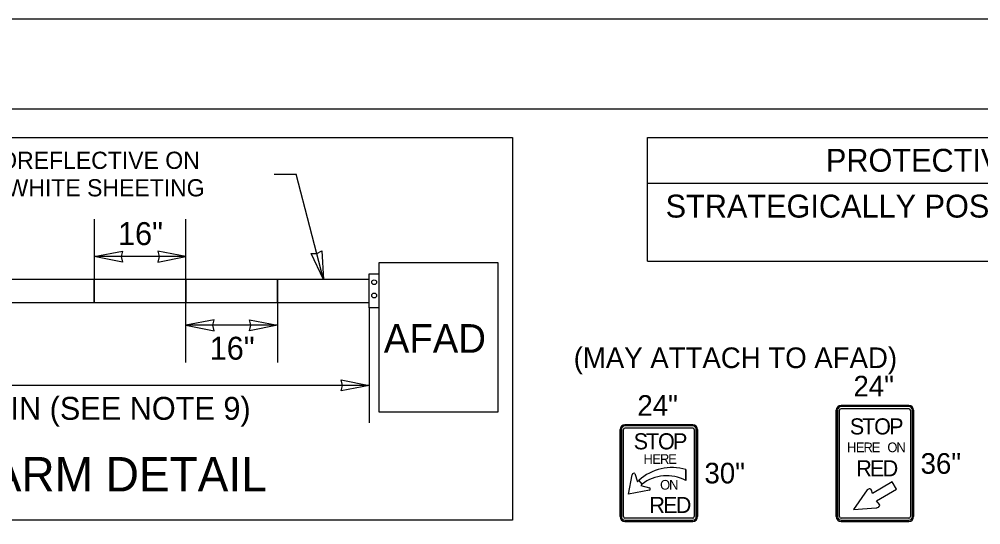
# Model space of a CAD drawing. Extents: x 99999.1 to 100095.7, y 99995 to 100010.7.
# Drawn here: x 100009.243 to 100012.598, y 100008.923 to 100010.687 of the extents above; entities that cross this region are included whole.
import ezdxf

# ---------------------------------------------------------------- set-up
doc = ezdxf.new("R2010")
doc.units = 0
for name, color, linetype in [('SH_GI_PlotLimits', 7, 'Continuous'), ('SH_GI_SheetBorder', 7, 'Continuous'), ('SH_TI_Tables', 7, 'Continuous'), ('TR_SN_ConstructionSigns', 7, 'Continuous'), ('TR_WZ_WorkZoneDetails', 7, 'Continuous')]:
    doc.layers.add(name, color=color, linetype=linetype)

msp = doc.modelspace()

# ---------------------------------------------------------------- linework, layer by layer
at = {"layer": 'SH_GI_PlotLimits'}
msp.add_lwpolyline([(99999.0625, 99999.6875), (100016.0625, 99999.6875), (100016.0625, 100010.6875), (99999.0625, 100010.6875)], close=True, dxfattribs=at)
at = {"layer": 'SH_GI_SheetBorder'}
msp.add_line((100000, 100010.375), (100015.75, 100010.375), dxfattribs=at)
at = {"layer": 'SH_TI_Tables'}
for p, q in [((100011.4347, 100009.843), (100011.4347, 100010.275)), ((100011.4347, 100010.275), (100015.65, 100010.275)), ((100011.4347, 100010.115), (100015.65, 100010.115)), ((100011.4347, 100009.843), (100015.65, 100009.843))]:
    msp.add_line(p, q, dxfattribs=at)
at = {"layer": 'TR_SN_ConstructionSigns'}
for p, q in [((100012.0939, 100009.3222), (100012.0939, 100008.951)), ((100012.0939, 100008.951), (100012.0939, 100009.3222)), ((100012.0939, 100009.3222), (100012.0939, 100008.951)), ((100012.0981, 100009.3222), (100012.0981, 100008.951)), ((100012.1052, 100008.951), (100012.1052, 100009.3222)), ((100012.347, 100009.3391), (100012.1108, 100009.3391)), ((100012.1108, 100009.3391), (100012.347, 100009.3391)), ((100012.347, 100009.3391), (100012.1108, 100009.3391)), ((100012.347, 100009.3349), (100012.1108, 100009.3349)), ((100012.1108, 100009.3279), (100012.347, 100009.3279)), ((100012.3527, 100009.3222), (100012.3527, 100008.951)), ((100012.3597, 100008.951), (100012.3597, 100009.3222)), ((100012.3639, 100008.951), (100012.3639, 100009.3222)), ((100012.3639, 100009.3222), (100012.3639, 100008.951)), ((100012.3639, 100008.951), (100012.3639, 100009.3222)), ((100011.3397, 100009.2547), (100011.3397, 100008.951)), ((100011.3397, 100008.951), (100011.3397, 100009.2547)), ((100011.3397, 100009.2547), (100011.3397, 100008.951)), ((100011.3397, 100008.951), (100011.3397, 100009.2547)), ((100011.3439, 100009.2547), (100011.3439, 100008.951)), ((100011.351, 100008.951), (100011.351, 100009.2547)), ((100011.5928, 100009.2716), (100011.3566, 100009.2716)), ((100011.3566, 100009.2716), (100011.5928, 100009.2716)), ((100011.5928, 100009.2716), (100011.3566, 100009.2716)), ((100011.3566, 100009.2716), (100011.5928, 100009.2716)), ((100011.5928, 100009.2674), (100011.3566, 100009.2674)), ((100011.3566, 100009.2604), (100011.5928, 100009.2604)), ((100011.5985, 100009.2547), (100011.5985, 100008.951)), ((100011.6055, 100008.951), (100011.6055, 100009.2547)), ((100011.6097, 100008.951), (100011.6097, 100009.2547)), ((100011.6097, 100009.2547), (100011.6097, 100008.951)), ((100011.6097, 100008.951), (100011.6097, 100009.2547)), ((100011.6097, 100009.2547), (100011.6097, 100008.951)), ((100011.5692, 100009.1152), (100011.5689, 100009.0774)), ((100011.5689, 100009.0774), (100011.5692, 100009.1152)), ((100011.3692, 100009.0297), (100011.3815, 100009.0967)), ((100011.3912, 100009.1011), (100011.3997, 100009.0719)), ((100011.3997, 100009.0719), (100011.4054, 100009.0776)), ((100011.4054, 100009.0776), (100011.4159, 100009.0642)), ((100011.4054, 100009.0776), (100011.4159, 100009.0642)), ((100011.4159, 100009.0642), (100011.4117, 100009.0599)), ((100011.4117, 100009.0599), (100011.4424, 100009.0517)), ((100012.289, 100009.0719), (100012.22, 100009.0321)), ((100012.234, 100009.0061), (100012.3037, 100009.0463)), ((100012.3037, 100009.0463), (100012.289, 100009.0719)), ((100011.4423, 100009.0433), (100011.3692, 100009.0297)), ((100012.2015, 100009.0445), (100012.1541, 100008.9764)), ((100012.22, 100009.0321), (100012.2166, 100009.0435)), ((100012.1541, 100008.9764), (100012.2332, 100008.9819)), ((100012.2451, 100008.9938), (100012.234, 100009.0061)), ((100011.5928, 100008.9454), (100011.3566, 100008.9454)), ((100012.347, 100008.9454), (100012.1108, 100008.9454)), ((100011.3566, 100008.9383), (100011.5928, 100008.9383)), ((100011.3566, 100008.9341), (100011.5928, 100008.9341)), ((100011.5928, 100008.9341), (100011.3566, 100008.9341)), ((100011.3566, 100008.9341), (100011.5928, 100008.9341)), ((100011.5928, 100008.9341), (100011.3566, 100008.9341)), ((100012.1108, 100008.9383), (100012.347, 100008.9383)), ((100012.1108, 100008.9341), (100012.347, 100008.9341)), ((100012.347, 100008.9341), (100012.1108, 100008.9341)), ((100012.1108, 100008.9341), (100012.347, 100008.9341))]:
    msp.add_line(p, q, dxfattribs=at)
for centre, radius, start, end in [((100012.1108, 100009.3222), 0.0169, 90, 180), ((100012.1108, 100009.3222), 0.0169, 90, 180), ((100012.1108, 100009.3222), 0.0169, 90, 180), ((100012.1108, 100009.3222), 0.0127, 90, 180), ((100012.1108, 100009.3222), 0.00562, 90, 180), ((100012.347, 100009.3222), 0.0169, 0, 90), ((100012.347, 100009.3222), 0.0169, 0, 90), ((100012.347, 100009.3222), 0.0169, 0, 90), ((100012.347, 100009.3222), 0.0127, 0, 90), ((100012.347, 100009.3222), 0.00562, 0, 90), ((100011.3566, 100009.2547), 0.0169, 90, 180), ((100011.3566, 100009.2547), 0.0169, 90, 180), ((100011.3566, 100009.2547), 0.0169, 90, 180), ((100011.3566, 100009.2547), 0.0169, 90, 180), ((100011.3566, 100009.2547), 0.0127, 90, 180), ((100011.3566, 100009.2547), 0.00562, 90, 180), ((100011.5928, 100009.2547), 0.0169, 0, 90), ((100011.5928, 100009.2547), 0.0169, 0, 90), ((100011.5928, 100009.2547), 0.0169, 0, 90), ((100011.5928, 100009.2547), 0.0169, 0, 90), ((100011.5928, 100009.2547), 0.0127, 0, 90), ((100011.5928, 100009.2547), 0.00562, 0, 90), ((100011.5208, 100008.9504), 0.1718, 73.6434, 132.2131), ((100011.5208, 100008.9504), 0.1718, 73.6434, 132.2131), ((100011.5028, 100008.9509), 0.1427, 62.4149, 127.4769), ((100011.5028, 100008.9509), 0.1427, 62.4149, 127.4769), ((100011.3566, 100008.951), 0.0169, 180, 270), ((100011.3566, 100008.951), 0.0169, 180, 270), ((100011.3566, 100008.951), 0.0169, 180, 270), ((100011.3566, 100008.951), 0.0169, 180, 270), ((100011.3566, 100008.951), 0.0127, 180, 270), ((100011.3566, 100008.951), 0.00562, 180, 270), ((100011.5928, 100008.951), 0.0169, 270, 0), ((100011.5928, 100008.951), 0.0169, 270, 0), ((100011.5928, 100008.951), 0.0169, 270, 0), ((100011.5928, 100008.951), 0.0127, 270, 0), ((100011.5928, 100008.951), 0.00562, 270, 0), ((100011.5928, 100008.951), 0.0169, 270, 0), ((100012.1108, 100008.951), 0.0169, 180, 270), ((100012.1108, 100008.951), 0.0169, 180, 270), ((100012.1108, 100008.951), 0.0169, 180, 270), ((100012.1108, 100008.951), 0.0127, 180, 270), ((100012.1108, 100008.951), 0.00562, 180, 270), ((100012.347, 100008.951), 0.0169, 270, 0), ((100012.347, 100008.951), 0.0169, 270, 0), ((100012.347, 100008.951), 0.0169, 270, 0), ((100012.347, 100008.951), 0.0127, 270, 0), ((100012.347, 100008.951), 0.00562, 270, 0)]:
    msp.add_arc(centre, radius, start, end, dxfattribs=at)
for centre, major_axis, ratio, start_param, end_param in [((100011.3873, 100009.0968), (-0.00583, -0.00008), 0.989437, 3.962549, 6.283185), ((100011.4403, 100009.0475), (-0.00414, 0.00215), 0.999053, 2.490568, 4.712389), ((100012.2076, 100009.0406), (0.00841, 0.00485), 0.700347, 5.977036, 8.198856), ((100012.2368, 100008.9893), (-0.00822, -0.00474), 0.700347, 0.771965, 3.092601)]:
    msp.add_ellipse(centre, major_axis=major_axis, ratio=ratio, start_param=start_param, end_param=end_param, dxfattribs=at)
at = {"layer": 'TR_WZ_WorkZoneDetails'}
for p, q in [((100010.1326, 100010.147), (100010.2088, 100010.147)), ((100010.3043, 100009.779), (100010.2088, 100010.147)), ((100009.5043, 100009.989), (100009.5043, 100009.779)), ((100009.8243, 100009.779), (100009.8243, 100009.989)), ((100009.8243, 100009.859), (100009.5043, 100009.859)), ((100009.8243, 100009.489), (100009.8243, 100009.699)), ((100010.1443, 100009.699), (100010.1443, 100009.489)), ((100010.4643, 100009.6797), (100010.4643, 100009.279)), ((100010.1443, 100009.619), (100009.8243, 100009.619)), ((100010.4643, 100009.409), (100008.6643, 100009.409))]:
    msp.add_line(p, q, dxfattribs=at)
for points in [[(100007.6374, 100010.275), (100010.9639, 100010.275), (100010.9639, 100008.939), (100007.6374, 100008.939)], [(100009.5043, 100009.859), (100009.6026, 100009.8783), (100009.5981, 100009.859), (100009.6026, 100009.8397)], [(100009.8243, 100009.859), (100009.7261, 100009.8783), (100009.7306, 100009.859), (100009.7261, 100009.8397)], [(100010.3043, 100009.779), (100010.2611, 100009.8693), (100010.2809, 100009.8697), (100010.2984, 100009.879)], [(100010.4643, 100009.7983), (100010.4977, 100009.7983), (100010.4977, 100009.6797), (100010.4643, 100009.6797)], [(100009.8243, 100009.619), (100009.9226, 100009.5997), (100009.9181, 100009.619), (100009.9226, 100009.6383)], [(100010.1443, 100009.619), (100010.0461, 100009.5997), (100010.0506, 100009.619), (100010.0461, 100009.6383)], [(100010.4643, 100009.409), (100010.3661, 100009.3897), (100010.3706, 100009.409), (100010.3661, 100009.4283)]]:
    msp.add_lwpolyline(points, close=True, dxfattribs=at)
for points in [[(100010.4977, 100009.6797), (100010.4977, 100009.3163), (100010.9139, 100009.3163), (100010.9139, 100009.8374), (100010.4977, 100009.8374), (100010.4977, 100009.7983), (100010.4977, 100009.6797)], [(100010.9139, 100009.8374), (100010.4977, 100009.8374), (100010.4977, 100009.3163), (100010.9139, 100009.3163), (100010.9139, 100009.8374)], [(100010.4643, 100009.779), (100008.6643, 100009.779), (100008.6643, 100009.699), (100010.4643, 100009.699), (100010.4643, 100009.779)], [(100009.1843, 100009.699), (100009.5043, 100009.699), (100009.5043, 100009.779), (100009.1843, 100009.779), (100009.1843, 100009.699)], [(100009.5043, 100009.699), (100009.8243, 100009.699), (100009.8243, 100009.779), (100009.5043, 100009.779), (100009.5043, 100009.699)], [(100009.8243, 100009.699), (100010.1443, 100009.699), (100010.1443, 100009.779), (100009.8243, 100009.779), (100009.8243, 100009.699)], [(100010.1443, 100009.699), (100010.4643, 100009.699), (100010.4643, 100009.779), (100010.1443, 100009.779), (100010.1443, 100009.699)]]:
    msp.add_lwpolyline(points, dxfattribs=at)
for centre, radius in [((100010.4813, 100009.7693), 0.00828), ((100010.4813, 100009.7229), 0.00855)]:
    msp.add_circle(centre, radius, dxfattribs=at)

# ---------------------------------------------------------------- texts
at = {"layer": 'SH_TI_Tables'}
for s, p in [('PROTECTIVE VEHICLE ROLL AHEAD DISTANCE = R', (100012.0577, 100010.155)), ('STRATEGICALLY POSITION WORK VEHICLE TO PROTECT WORK CREW.', (100011.4984, 100009.995))]:
    msp.add_text(s, height=0.08, rotation=360, dxfattribs=at).set_placement(p)
at = {"layer": 'TR_SN_ConstructionSigns'}
for s, p in [('(MAY ATTACH TO AFAD)', (100011.1775, 100009.4696)), ('24"', (100012.1539, 100009.3706)), ('24"', (100011.3999, 100009.3031)), ('36"', (100012.3882, 100009.1006)), ('30"', (100011.634, 100009.0669))]:
    msp.add_text(s, height=0.072, rotation=360, dxfattribs=at).set_placement(p)
for s, height, p in [('S', 0.0562, (100012.1412, 100009.2379)), ('T', 0.0562, (100012.1839, 100009.2379)), ('O', 0.0562, (100012.2261, 100009.2379)), ('P', 0.0562, (100012.2784, 100009.2379)), ('S', 0.0562, (100011.387, 100009.1858)), ('T', 0.0562, (100011.4297, 100009.1858)), ('O', 0.0562, (100011.4719, 100009.1858)), ('P', 0.0562, (100011.5242, 100009.1858)), ('H', 0.0338, (100012.1312, 100009.176)), ('E', 0.0338, (100012.1623, 100009.176)), ('R', 0.0338, (100012.1889, 100009.176)), ('E', 0.0338, (100012.2176, 100009.176)), ('O', 0.0338, (100012.2723, 100009.176)), ('N', 0.0338, (100012.3037, 100009.176)), ('H', 0.0338, (100011.421, 100009.1352)), ('E', 0.0338, (100011.4521, 100009.1352)), ('R', 0.0338, (100011.4788, 100009.1352)), ('E', 0.0338, (100011.5074, 100009.1352)), ('R', 0.0562, (100012.1637, 100009.0916)), ('E', 0.0562, (100012.2115, 100009.0916)), ('D', 0.0562, (100012.2559, 100009.0916)), ('O', 0.0338, (100011.4791, 100009.0452)), ('N', 0.0338, (100011.5105, 100009.0452)), ('R', 0.0562, (100011.4417, 100008.9636)), ('E', 0.0562, (100011.4895, 100008.9636)), ('D', 0.0562, (100011.5339, 100008.9636))]:
    msp.add_text(s, height=height, dxfattribs=at).set_placement(p)
at = {"layer": 'TR_WZ_WorkZoneDetails'}
for s, height, p in [('GATE ARM SHALL BE FULLY RETROREFLECTIVE ON', 0.06, (100007.8352, 100010.165)), ('BOTH SIDES WITH ALTERNATING RED/WHITE SHEETING', 0.06, (100007.6874, 100010.069)), ('16"', 0.08, (100009.5873, 100009.899)), ('AFAD', 0.1, (100010.5149, 100009.5231)), ('16"', 0.08, (100009.9073, 100009.499)), ('78" MIN (SEE NOTE 9)', 0.08, (100008.9363, 100009.289))]:
    msp.add_text(s, height=height, dxfattribs=at).set_placement(p)
msp.add_text('AFAD GATE ARM DETAIL', height=0.12, rotation=360, dxfattribs=at).set_placement((100008.1893, 100009.039))

doc.saveas('drawing.dxf')
